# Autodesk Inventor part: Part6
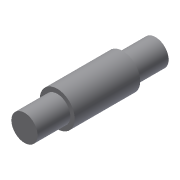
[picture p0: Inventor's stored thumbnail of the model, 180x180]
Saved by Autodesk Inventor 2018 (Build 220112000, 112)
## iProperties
Shininess: 77.0
Length Units: 11269
Angle Units: 11279
Time Units: 11290
Mass Units: 11283
Length Display Precision: 3
Angle Display Precision: 2
Created: 2002-01
Part Number: Part6
Document SubType Name: Modeling
Designer: ***
Density: 1 g/cm^3
Material: Generic
Appearance: Default
Density: 0.0
Volumn: 0.0
Area: 0.0
PropertySet Name: Model Information
Control State: 0
Master: False
Checked Out: False
Author: ***
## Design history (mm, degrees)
sketch "Sketch1"
  geometry: L1 (1.545, 32.521)-(-4.455, 32.521); L2 (-4.455, 32.521)-(-4.455, 17.521); L3 (-4.455, 17.521)-(-6.455, 17.521); L4 (-6.455, 17.521)-(-6.455, -12.479); L5 (-6.455, -12.479)-(-4.455, -12.479); L6 (-4.455, -12.479)-(-4.455, -27.479); L7 (-4.455, -27.479)-(1.545, -27.479); L8 (1.545, -27.479)-(1.545, 32.521)
  constraints: 16 end point, 5 parallel, 2 equal length, 1 collinear, 1 horizontal, 1 perpendicular
  dimensions: "d0" = 16 diameter of L4 L8; "d1" = 12 diameter of L2 L8; "d2" = 60 distance of L7.end L1.start; "d3" = 30 distance of L3.end L4.end
revolve "Revolution1" sketch "Sketch1" stored, may be unused: angle "d4" = 90 deg
body "Solid1"
